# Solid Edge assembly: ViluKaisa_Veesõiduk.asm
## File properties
Author: kaisa
Template: Iso Metric Assembly.asm
Last saved by: kaisa
Revision: 27
Application: Solid Edge
Username: kaisa
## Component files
ViluKaisa_mast_v2ike.par
ViluKaisa_Purje_suur.par
ViluKaisa_Lipp.par
ViluKaisa_Trepp.psm
ViluKaisa_Purje_v2ike.par
ViluKaisa_reelingupost.par
reelingupost_mir.par
ViluKaisa_Trepikatus.par
ViluKaisa_reelingukois.par
ViluKaisa_Parras.par
ViluKaisa_Emapuu.par
ViluKaisa_Ribid.par
ViluKaisa_Ribid_mir.par
ViluKaisa_Parras_mir.par
ViluKaisa_mast_suur.par
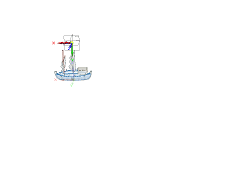
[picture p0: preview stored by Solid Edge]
